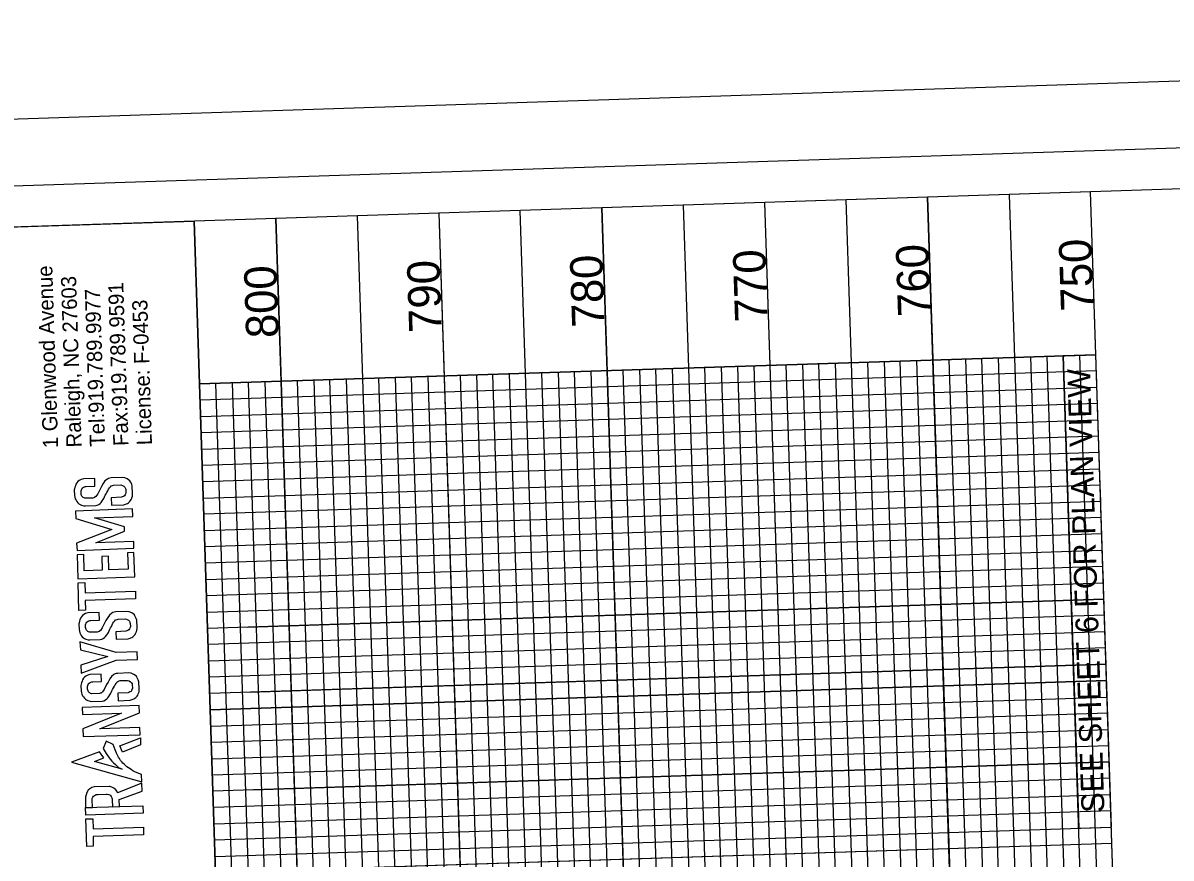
# Model space of a CAD drawing. Extents: x 1627314 to 1628469, y 762309 to 764245.
# Drawn here: x 1627512.6 to 1627864.7, y 763788.2 to 764044.4 of the extents above; entities that cross this region are included whole.
import ezdxf

# ---------------------------------------------------------------- set-up
doc = ezdxf.new("R2010")
doc.units = 0
for name, color, linetype in [('Exist Vertical Profile Vertical Axis Label', 7, 'Continuous'), ('Old_Level_2', 7, 'Continuous'), ('Prop DSN Text', 7, 'Continuous'), ('Prop Grid Mask', 7, 'Continuous'), ('Sheet DOT Grid CELL', 7, 'Continuous'), ('Sheet Layout Profile Border Port 1', 7, 'Continuous'), ('Sheet Plot Border Inside CELL', 7, 'Continuous'), ('Sheet Plot Border Outside CELL', 7, 'Continuous'), ('Sheet Profile CELL', 7, 'Continuous'), ('Sheet Profile Grid Major CELL', 7, 'Continuous'), ('Sheet Profile Grid Middle CELL', 7, 'Continuous'), ('Sheet Profile Grid Minor CELL', 7, 'Continuous')]:
    doc.layers.add(name, color=color, linetype=linetype)

msp = doc.modelspace()

# ---------------------------------------------------------------- linework, layer by layer
at = {"layer": 'Old_Level_2'}
for points in [[(1627507.79, 763781.61), (1627501.25, 763981.49), (1627565.16, 763983.58), (1627571.7, 763783.7)], [(1627534.7, 763902.32), (1627534.62, 763904.63), (1627531.15, 763904.51), (1627530.45, 763904.29), (1627529.87, 763903.99), (1627529.49, 763903.68), (1627529.15, 763903.3), (1627528.88, 763902.85), (1627528.72, 763902.42), (1627528.72, 763902.42), (1627528.54, 763901.95), (1627528.44, 763901.47), (1627528.37, 763901.14), (1627528.46, 763899.4), (1627528.57, 763898.87), (1627528.66, 763898.42), (1627528.92, 763897.96), (1627529.14, 763897.57), (1627529.44, 763897.18), (1627529.76, 763896.88), (1627530.13, 763896.65), (1627530.53, 763896.47), (1627531.24, 763896.24), (1627531.76, 763896.2), (1627534.92, 763896.31), (1627535.4, 763896.44), (1627535.88, 763896.68), (1627536.28, 763896.99), (1627536.58, 763897.29), (1627536.92, 763897.76), (1627537.25, 763898.22), (1627537.46, 763898.51), (1627537.67, 763899), (1627537.88, 763899.49), (1627538.12, 763899.89), (1627538.39, 763900.34), (1627538.64, 763900.87), (1627538.84, 763901.31), (1627539.14, 763901.75), (1627539.43, 763902.07), (1627539.66, 763902.33), (1627540.13, 763902.5), (1627540.43, 763902.6), (1627542.67, 763902.64), (1627543.16, 763902.5), (1627543.58, 763902.27), (1627543.88, 763901.95), (1627544.06, 763901.6), (1627544.14, 763901.26), (1627544.19, 763900.3), (1627544.11, 763899.97), (1627543.93, 763899.64), (1627543.75, 763899.3), (1627543.42, 763899.15), (1627543.09, 763899), (1627542.82, 763898.88), (1627539.71, 763898.74), (1627539.82, 763896.4), (1627543.52, 763896.57), (1627543.8, 763896.69), (1627544.65, 763896.99), (1627544.94, 763897.18), (1627545.25, 763897.44), (1627545.61, 763897.83), (1627545.8, 763898.14), (1627545.96, 763898.58), (1627546.03, 763898.74), (1627546.19, 763899.18), (1627546.23, 763899.72), (1627546.25, 763900.11), (1627546.13, 763902.25), (1627545.97, 763902.84), (1627545.57, 763903.65), (1627545.43, 763903.93), (1627544.62, 763904.52), (1627543.83, 763904.83), (1627543.11, 763904.96), (1627539.69, 763904.8), (1627539.22, 763904.77), (1627538.85, 763904.63), (1627538.5, 763904.43), (1627537.76, 763903.86), (1627537.23, 763903.14), (1627536.68, 763902.14), (1627536.26, 763901.39), (1627535.54, 763899.9), (1627535.01, 763899.13), (1627534.59, 763898.78), (1627534.31, 763898.7), (1627534.03, 763898.61), (1627531.6, 763898.58), (1627531.34, 763898.69), (1627531.08, 763898.81), (1627530.93, 763898.98), (1627530.72, 763899.21), (1627530.61, 763899.46), (1627530.49, 763899.72), (1627530.52, 763899.86), (1627530.44, 763899.88), (1627530.42, 763900.84), (1627530.53, 763901.12), (1627530.63, 763901.4), (1627530.73, 763901.68), (1627530.91, 763901.81), (1627531.19, 763902.01), (1627531.46, 763902.11), (1627531.73, 763902.21), (1627532.04, 763902.21)], [(1627539.83, 763888.95), (1627529.04, 763884.78), (1627529.22, 763882.58), (1627546.67, 763883.23), (1627546.59, 763885.34), (1627534.92, 763884.9), (1627543.79, 763888.46), (1627543.78, 763889.81), (1627534.56, 763892.58), (1627546.27, 763893), (1627546.19, 763895.28), (1627528.78, 763894.65), (1627528.86, 763892.35)], [(1627529.23, 763881.22), (1627529.48, 763873.84), (1627546.89, 763874.43), (1627546.64, 763881.9), (1627544.67, 763881.83), (1627544.84, 763876.79), (1627539, 763876.59), (1627538.86, 763880.8), (1627536.79, 763880.73), (1627536.93, 763876.49), (1627531.44, 763876.3), (1627531.27, 763881.31)], [(1627529.79, 763864.16), (1627529.51, 763872.62), (1627531.58, 763872.69), (1627531.69, 763869.58), (1627547.1, 763870.1), (1627547.18, 763867.75), (1627531.66, 763867.23), (1627531.76, 763864.26)], [(1627536.08, 763861.21), (1627536.01, 763863.52), (1627532.53, 763863.4), (1627531.83, 763863.18), (1627531.25, 763862.88), (1627530.87, 763862.57), (1627530.53, 763862.19), (1627530.26, 763861.74), (1627530.1, 763861.31), (1627530.1, 763861.31), (1627529.93, 763860.84), (1627529.82, 763860.36), (1627529.75, 763860.03), (1627529.84, 763858.29), (1627529.95, 763857.76), (1627530.04, 763857.31), (1627530.3, 763856.85), (1627530.52, 763856.46), (1627530.82, 763856.07), (1627531.14, 763855.77), (1627531.52, 763855.54), (1627531.92, 763855.36), (1627532.62, 763855.13), (1627533.14, 763855.09), (1627536.31, 763855.2), (1627536.78, 763855.33), (1627537.26, 763855.58), (1627537.67, 763855.88), (1627537.97, 763856.18), (1627538.3, 763856.65), (1627538.63, 763857.11), (1627538.84, 763857.4), (1627539.05, 763857.89), (1627539.26, 763858.38), (1627539.5, 763858.78), (1627539.77, 763859.23), (1627540.02, 763859.77), (1627540.23, 763860.21), (1627540.53, 763860.65), (1627540.81, 763860.96), (1627541.04, 763861.22), (1627541.52, 763861.39), (1627541.81, 763861.5), (1627544.05, 763861.53), (1627544.54, 763861.39), (1627544.97, 763861.16), (1627545.27, 763860.84), (1627545.44, 763860.49), (1627545.52, 763860.15), (1627545.57, 763859.19), (1627545.49, 763858.87), (1627545.31, 763858.53), (1627545.13, 763858.2), (1627544.8, 763858.04), (1627544.47, 763857.89), (1627544.21, 763857.77), (1627541.1, 763857.63), (1627541.2, 763855.29), (1627544.91, 763855.46), (1627545.19, 763855.58), (1627546.04, 763855.88), (1627546.32, 763856.07), (1627546.63, 763856.33), (1627547, 763856.72), (1627547.18, 763857.03), (1627547.35, 763857.48), (1627547.41, 763857.64), (1627547.58, 763858.07), (1627547.61, 763858.61), (1627547.64, 763859), (1627547.51, 763861.14), (1627547.35, 763861.73), (1627546.95, 763862.54), (1627546.82, 763862.82), (1627546.01, 763863.41), (1627545.21, 763863.72), (1627544.49, 763863.85), (1627541.08, 763863.69), (1627540.6, 763863.66), (1627540.23, 763863.52), (1627539.88, 763863.32), (1627539.14, 763862.75), (1627538.61, 763862.03), (1627538.06, 763861.04), (1627537.64, 763860.28), (1627536.92, 763858.79), (1627536.39, 763858.02), (1627535.98, 763857.67), (1627535.7, 763857.59), (1627535.42, 763857.5), (1627532.98, 763857.47), (1627532.73, 763857.58), (1627532.47, 763857.7), (1627532.31, 763857.87), (1627532.11, 763858.1), (1627531.99, 763858.35), (1627531.87, 763858.61), (1627531.9, 763858.75), (1627531.82, 763858.77), (1627531.81, 763859.73), (1627531.91, 763860.01), (1627532.01, 763860.29), (1627532.11, 763860.57), (1627532.3, 763860.7), (1627532.57, 763860.9), (1627532.84, 763861), (1627533.12, 763861.1), (1627533.42, 763861.1)], [(1627530.37, 763847.41), (1627530.45, 763844.88), (1627541.21, 763848.85), (1627547.75, 763849.09), (1627547.66, 763851.48), (1627541.17, 763851.24), (1627530.09, 763854.54), (1627530.24, 763852.05), (1627538.66, 763850.01)], [(1627536.72, 763842.35), (1627536.64, 763844.65), (1627533.16, 763844.54), (1627532.47, 763844.32), (1627531.89, 763844.02), (1627531.51, 763843.71), (1627531.17, 763843.33), (1627530.9, 763842.88), (1627530.74, 763842.45), (1627530.74, 763842.45), (1627530.56, 763841.98), (1627530.45, 763841.5), (1627530.38, 763841.17), (1627530.48, 763839.43), (1627530.59, 763838.9), (1627530.68, 763838.45), (1627530.93, 763837.99), (1627531.16, 763837.6), (1627531.46, 763837.21), (1627531.78, 763836.91), (1627532.15, 763836.68), (1627532.55, 763836.5), (1627533.26, 763836.27), (1627533.77, 763836.23), (1627536.94, 763836.34), (1627537.41, 763836.47), (1627537.9, 763836.71), (1627538.3, 763837.02), (1627538.6, 763837.32), (1627538.93, 763837.78), (1627539.27, 763838.25), (1627539.48, 763838.54), (1627539.69, 763839.03), (1627539.89, 763839.52), (1627540.13, 763839.92), (1627540.41, 763840.37), (1627540.66, 763840.9), (1627540.86, 763841.34), (1627541.16, 763841.78), (1627541.45, 763842.1), (1627541.68, 763842.36), (1627542.15, 763842.53), (1627542.45, 763842.63), (1627544.68, 763842.67), (1627545.17, 763842.53), (1627545.6, 763842.3), (1627545.9, 763841.98), (1627546.07, 763841.63), (1627546.16, 763841.29), (1627546.21, 763840.33), (1627546.13, 763840), (1627545.95, 763839.67), (1627545.76, 763839.33), (1627545.43, 763839.18), (1627545.1, 763839.03), (1627544.84, 763838.91), (1627541.73, 763838.77), (1627541.84, 763836.43), (1627545.54, 763836.6), (1627545.82, 763836.72), (1627546.67, 763837.02), (1627546.96, 763837.21), (1627547.27, 763837.47), (1627547.63, 763837.86), (1627547.81, 763838.17), (1627547.98, 763838.61), (1627548.04, 763838.77), (1627548.21, 763839.21), (1627548.25, 763839.75), (1627548.27, 763840.14), (1627548.15, 763842.28), (1627547.99, 763842.87), (1627547.59, 763843.68), (1627547.45, 763843.95), (1627546.64, 763844.55), (1627545.84, 763844.86), (1627545.13, 763844.99), (1627541.71, 763844.83), (1627541.24, 763844.8), (1627540.87, 763844.66), (1627540.52, 763844.46), (1627539.78, 763843.89), (1627539.24, 763843.17), (1627538.7, 763842.17), (1627538.28, 763841.42), (1627537.56, 763839.93), (1627537.02, 763839.15), (1627536.61, 763838.81), (1627536.33, 763838.73), (1627536.05, 763838.64), (1627533.62, 763838.61), (1627533.36, 763838.72), (1627533.1, 763838.84), (1627532.94, 763839.01), (1627532.74, 763839.23), (1627532.62, 763839.49), (1627532.51, 763839.75), (1627532.53, 763839.89), (1627532.46, 763839.91), (1627532.44, 763840.86), (1627532.54, 763841.15), (1627532.64, 763841.43), (1627532.74, 763841.71), (1627532.93, 763841.84), (1627533.2, 763842.04), (1627533.48, 763842.14), (1627533.75, 763842.24), (1627534.06, 763842.24)], [(1627531.1, 763825.45), (1627548.55, 763826.04), (1627548.47, 763828.28), (1627536.2, 763827.86), (1627548.35, 763832.72), (1627548.25, 763834.96), (1627530.75, 763834.37), (1627530.83, 763832.19), (1627542.8, 763832.6), (1627531.01, 763827.81)], [(1627527.54, 763817.56), (1627549.08, 763811.6), (1627548.99, 763813.82), (1627548.14, 763814.14), (1627546.97, 763814.67), (1627546.33, 763814.96), (1627545.78, 763815.32), (1627545, 763815.82), (1627544.52, 763816.13), (1627544.12, 763816.5), (1627543.71, 763816.86), (1627543.2, 763817.33), (1627542.92, 763817.74), (1627542.57, 763818.14), (1627542.23, 763818.69), (1627541.93, 763819.17), (1627541.33, 763820.37), (1627540.88, 763821.35), (1627540.27, 763822.98), (1627538.09, 763824.04), (1627537.21, 763821.84), (1627538.15, 763820.23), (1627539.1, 763818.89), (1627539.92, 763817.93), (1627540.37, 763817.42), (1627540.95, 763816.91), (1627541.54, 763816.39), (1627541.97, 763816.01), (1627542.63, 763815.65), (1627543, 763815.45), (1627534.54, 763817.81), (1627537.4, 763818.9), (1627536.08, 763820.75)], [(1627543.15, 763820.69), (1627542.32, 763822.58), (1627548.68, 763825.05), (1627548.67, 763822.95)], [(1627533.93, 763803.74), (1627533.85, 763806.13), (1627533.89, 763806.43), (1627534.04, 763806.84), (1627534.24, 763807.17), (1627534.51, 763807.41), (1627534.83, 763807.58), (1627535.09, 763807.71), (1627535.67, 763807.73), (1627538.16, 763807.82), (1627538.49, 763807.77), (1627538.94, 763807.7), (1627539.23, 763807.58), (1627539.5, 763807.38), (1627539.72, 763807.12), (1627539.89, 763806.7), (1627539.94, 763806.38), (1627539.99, 763806.05), (1627540.07, 763803.95), (1627542.18, 763804.03), (1627542.1, 763806.13), (1627549.18, 763808.74), (1627549.07, 763811.15), (1627541.63, 763808.25), (1627541.48, 763808.63), (1627541.06, 763809.15), (1627540.51, 763809.62), (1627539.87, 763809.95), (1627539.23, 763810.14), (1627539.04, 763810.12), (1627534.48, 763810.01), (1627533.74, 763809.79), (1627533.08, 763809.4), (1627532.62, 763808.98), (1627532.17, 763808.26), (1627531.96, 763807.58), (1627531.76, 763806.89), (1627531.77, 763806.49), (1627531.84, 763803.67)], [(1627531.92, 763801.36), (1627531.84, 763803.67), (1627549.4, 763804.26), (1627549.48, 763801.95)], [(1627532.23, 763791.74), (1627531.95, 763800.2), (1627534.02, 763800.27), (1627534.12, 763797.16), (1627549.54, 763797.68), (1627549.62, 763795.33), (1627534.1, 763794.81), (1627534.2, 763791.84)]]:
    msp.add_lwpolyline(points, close=True, dxfattribs=at)
at = {"layer": 'Prop Grid Mask'}
msp.add_lwpolyline([(1627831.66, 763942.29), (1627836.4, 763797.36), (1627846.39, 763797.69), (1627841.65, 763942.61)], close=True, dxfattribs=at)
at = {"layer": 'Sheet DOT Grid CELL'}
for p, q in [((1627740.07, 763989.32), (1627789.11, 762490.12)), ((1627790.04, 763990.95), (1627839.08, 762491.75)), ((1627640.12, 763986.05), (1627689.16, 762486.85)), ((1627690.1, 763987.68), (1627739.13, 762488.48)), ((1627590.15, 763984.41), (1627639.19, 762485.21)), ((1627841.65, 763942.61), (1627566.8, 763933.62)), ((1627843.28, 763892.64), (1627568.43, 763883.65)), ((1627844.92, 763842.67), (1627570.07, 763833.68)), ((1627846.55, 763792.69), (1627484.3, 763780.84))]:
    msp.add_line(p, q, dxfattribs=at)
at = {"layer": 'Sheet Layout Profile Border Port 1'}
msp.add_lwpolyline([(1627548.65, 762532.28), (1627887.42, 762543.36), (1627841.65, 763942.61), (1627566.8, 763933.62)], dxfattribs=at)
at = {"layer": 'Sheet Plot Border Inside CELL'}
msp.add_lwpolyline([(1628446.34, 762357.53), (1628391.86, 764023.14), (1627337.33, 763988.65), (1627391.81, 762323.04)], close=True, dxfattribs=at)
at = {"layer": 'Sheet Plot Border Outside CELL'}
msp.add_lwpolyline([(1628469.21, 762345.27), (1628413.63, 764044.37), (1627314.22, 764008.4), (1627369.79, 762309.31)], close=True, dxfattribs=at)
at = {"layer": 'Sheet Profile CELL'}
msp.add_line((1627889.05, 762493.39), (1627840.02, 763992.59), dxfattribs=at)
msp.add_lwpolyline([(1627340.28, 763976.24), (1627389.32, 762477.04), (1628438.76, 762511.37), (1628389.72, 764010.57)], close=True, dxfattribs=at)
at = {"layer": 'Sheet Profile Grid Major CELL'}
for points in [[(1627566.8, 763933.62), (1627841.65, 763942.61), (1627840.02, 763992.59), (1627490.2, 763981.14)], [(1627740.07, 763989.32), (1627789.11, 762490.12), (1627789.11, 762490.12), (1627839.08, 762491.75), (1627790.04, 763990.95)], [(1627640.12, 763986.05), (1627689.16, 762486.85), (1627739.13, 762488.48), (1627690.1, 763987.68)], [(1627546.71, 763782.88), (1627589.21, 762483.58), (1627639.19, 762485.21), (1627590.15, 763984.41)], [(1627570.07, 763833.68), (1627844.92, 763842.67), (1627843.28, 763892.64), (1627843.28, 763892.64), (1627568.43, 763883.65)], [(1627864.53, 763242.99), (1627862.9, 763292.96), (1627363.17, 763276.61), (1627361.53, 763326.59), (1627861.27, 763342.93), (1627859.63, 763392.91), (1627359.9, 763376.56), (1627358.26, 763426.53), (1627858, 763442.88), (1627856.36, 763492.85), (1627356.63, 763476.51), (1627354.99, 763526.48), (1627854.73, 763542.83), (1627853.09, 763592.8), (1627353.36, 763576.45), (1627351.73, 763626.43), (1627851.46, 763642.77), (1627849.82, 763692.75), (1627350.09, 763676.4), (1627348.46, 763726.37), (1627848.19, 763742.72), (1627846.55, 763792.69), (1627346.82, 763776.35), (1627345.96, 763802.63)]]:
    msp.add_lwpolyline(points, dxfattribs=at)
at = {"layer": 'Sheet Profile Grid Middle CELL'}
for points in [[(1627715.08, 763988.5), (1627764.12, 762489.3), (1627814.09, 762490.94), (1627765.06, 763990.13)], [(1627815.03, 763991.77), (1627864.07, 762492.57)], [(1627615.14, 763985.23), (1627664.17, 762486.03), (1627714.15, 762487.67), (1627665.11, 763986.86)], [(1627570.88, 763808.69), (1627565.16, 763983.6)], [(1627581.44, 763859.06), (1627844.1, 763867.65), (1627842.47, 763917.63), (1627567.61, 763908.64)], [(1627583.08, 763809.09), (1627845.74, 763817.68), (1627844.1, 763867.65), (1627569.25, 763858.66)], [(1627863.72, 763267.97), (1627862.08, 763317.95), (1627362.35, 763301.6), (1627360.72, 763351.57), (1627860.45, 763367.92), (1627858.81, 763417.89), (1627359.08, 763401.55), (1627357.45, 763451.52), (1627857.18, 763467.87), (1627855.54, 763517.84), (1627355.81, 763501.49), (1627354.18, 763551.47), (1627853.91, 763567.81), (1627852.28, 763617.79), (1627352.54, 763601.44), (1627350.91, 763651.41), (1627850.64, 763667.76), (1627849.01, 763717.73), (1627349.27, 763701.39), (1627347.64, 763751.36), (1627847.37, 763767.71), (1627845.74, 763817.68), (1627570.88, 763808.69)], [(1627521.73, 763782.02), (1627564.23, 762482.76), (1627614.2, 762484.4), (1627570.88, 763808.69)]]:
    msp.add_lwpolyline(points, dxfattribs=at)
at = {"layer": 'Sheet Profile Grid Minor CELL'}
for p, q in [((1627761.69, 763940), (1627807.46, 762540.75)), ((1627817.46, 762541.07), (1627771.69, 763940.32)), ((1627776.69, 763940.49), (1627822.45, 762541.24)), ((1627827.45, 762541.4), (1627781.68, 763940.65)), ((1627786.68, 763940.81), (1627832.45, 762541.56)), ((1627842.44, 762541.89), (1627796.67, 763941.14)), ((1627801.67, 763941.3), (1627847.44, 762542.05)), ((1627852.44, 762542.22), (1627806.67, 763941.47)), ((1627811.67, 763941.63), (1627857.44, 762542.38)), ((1627867.43, 762542.71), (1627821.66, 763941.96)), ((1627826.66, 763942.12), (1627872.43, 762542.87)), ((1627877.42, 762543.03), (1627831.66, 763942.29)), ((1627702.52, 762537.31), (1627656.75, 763936.56)), ((1627661.75, 763936.73), (1627707.52, 762537.48)), ((1627717.51, 762537.8), (1627671.74, 763937.05)), ((1627676.74, 763937.22), (1627722.51, 762537.97)), ((1627727.51, 762538.13), (1627681.74, 763937.38)), ((1627686.73, 763937.55), (1627732.5, 762538.29)), ((1627742.5, 762538.62), (1627696.73, 763937.87)), ((1627701.73, 763938.04), (1627747.49, 762538.78)), ((1627752.49, 762538.95), (1627706.72, 763938.2)), ((1627711.72, 763938.36), (1627757.49, 762539.11)), ((1627767.48, 762539.44), (1627721.71, 763938.69)), ((1627726.71, 763938.85), (1627772.48, 762539.6)), ((1627731.71, 763939.02), (1627777.48, 762539.76)), ((1627736.71, 763939.18), (1627782.48, 762539.93)), ((1627792.47, 762540.25), (1627746.7, 763939.51)), ((1627751.7, 763939.67), (1627797.47, 762540.42)), ((1627802.47, 762540.58), (1627756.7, 763939.83)), ((1627576.79, 763933.95), (1627622.56, 762534.7)), ((1627627.56, 762534.86), (1627581.79, 763934.11)), ((1627586.79, 763934.28), (1627632.56, 762535.02)), ((1627642.55, 762535.35), (1627596.78, 763934.6)), ((1627601.78, 763934.77), (1627647.55, 762535.51)), ((1627652.55, 762535.68), (1627606.78, 763934.93)), ((1627611.77, 763935.09), (1627657.54, 762535.84)), ((1627667.54, 762536.17), (1627621.77, 763935.42)), ((1627626.77, 763935.58), (1627672.53, 762536.33)), ((1627677.53, 762536.5), (1627631.76, 763935.75)), ((1627636.76, 763935.91), (1627682.53, 762536.66)), ((1627692.52, 762536.99), (1627646.75, 763936.24)), ((1627651.75, 763936.4), (1627697.52, 762537.15))]:
    msp.add_line(p, q, dxfattribs=at)
for points in [[(1627836.65, 763942.45), (1627882.42, 762543.2)], [(1627567.12, 763923.63), (1627841.98, 763932.62), (1627841.81, 763937.62), (1627566.96, 763928.62)], [(1627566.71, 763783.49), (1627607.57, 762534.21), (1627617.56, 762534.53), (1627571.79, 763933.79)], [(1627567.45, 763913.63), (1627842.3, 763922.62), (1627842.14, 763927.62), (1627567.29, 763918.63)], [(1627567.94, 763898.64), (1627842.79, 763907.63), (1627842.63, 763912.63), (1627567.78, 763903.64)], [(1627568.27, 763888.65), (1627843.12, 763897.64), (1627842.96, 763902.63), (1627568.1, 763893.64)], [(1627568.76, 763873.65), (1627843.61, 763882.64), (1627843.45, 763887.64), (1627568.6, 763878.65)], [(1627569.09, 763863.66), (1627843.94, 763872.65), (1627843.78, 763877.65), (1627568.92, 763868.66)], [(1627569.58, 763848.67), (1627844.43, 763857.66), (1627844.27, 763862.66), (1627569.41, 763853.66)], [(1627582.1, 763839.07), (1627844.76, 763847.66), (1627844.59, 763852.66), (1627569.74, 763843.67)], [(1627570.23, 763828.65), (1627845.04, 763837.57), (1627844.87, 763842.56), (1627844.76, 763847.66), (1627569.9, 763838.67)], [(1627570.72, 763813.69), (1627845.57, 763822.68), (1627845.57, 763822.68), (1627845.41, 763827.67), (1627845.25, 763832.67), (1627570.39, 763823.68)], [(1627570.56, 763818.68), (1627845.41, 763827.67)], [(1627571.21, 763798.69), (1627846.06, 763807.68), (1627845.9, 763812.68), (1627571.05, 763803.69)], [(1627571.54, 763788.7), (1627846.39, 763797.69), (1627846.23, 763802.69), (1627571.37, 763793.7)]]:
    msp.add_lwpolyline(points, dxfattribs=at)

# ---------------------------------------------------------------- texts
at = {"layer": 'Exist Vertical Profile Vertical Axis Label'}
for s, p in [('760', (1627790.99, 763954.39)), ('750', (1627840.96, 763956.03)), ('780', (1627691.04, 763951.13)), ('770', (1627741.01, 763952.76)), ('800', (1627591.09, 763947.86)), ('790', (1627641.07, 763949.49))]:
    msp.add_text(s, height=10, rotation=91.8735, dxfattribs=at).set_placement(p)
at = {"layer": 'Old_Level_2'}
for s, p in [('1 Glenwood Avenue', (1627523.43, 763913.98)), ('Raleigh, NC 27603', (1627530.62, 763914.21)), ('Tel:919.789.9977 ', (1627537.81, 763914.45)), ('Fax:919.789.9591', (1627545.01, 763914.68)), ('License: F-0453', (1627552.2, 763914.92))]:
    msp.add_text(s, height=4.6576, rotation=91.8735, dxfattribs=at).set_placement(p)
at = {"layer": 'Prop DSN Text'}
msp.add_text('SEE SHEET 6 FOR PLAN VIEW', height=7, rotation=91.8735, dxfattribs=at).set_placement((1627844.29, 763802.2))

doc.saveas('drawing.dxf')
